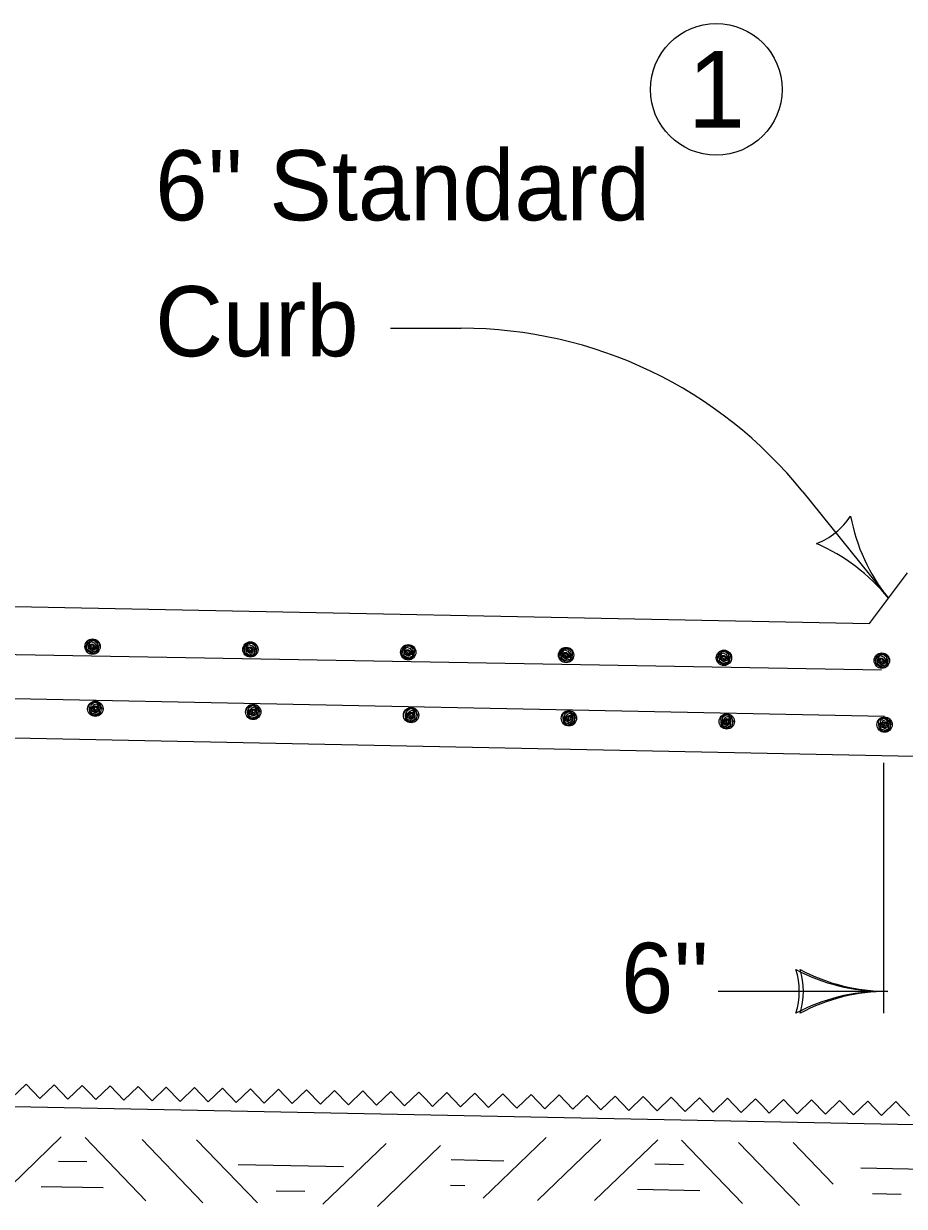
# Model space of a CAD drawing. Extents: x 10133 to 81668, y 7924 to 11018.
# Drawn here: x 11028.4 to 11229.3, y 8273.3 to 8543 of the extents above; entities that cross this region are included whole.
import ezdxf

# ---------------------------------------------------------------- set-up
doc = ezdxf.new("R2010")
doc.units = 0
doc.layers.add('BridgeExistingStructure', color=7, linetype='Continuous')
doc.layers.add('RasterAttachment', color=7, linetype='Continuous')

msp = doc.modelspace()

# ---------------------------------------------------------------- linework, layer by layer
at = {"layer": 'RasterAttachment'}
for p, q in [((11112.11, 8473.58), (11128.23, 8473.58)), ((11206.12, 8436.29), (11225.66, 8412.01)), ((10451.65, 8421.69), (11221.33, 8406.24)), ((11221.33, 8406.24), (11229.99, 8417.79)), ((10468, 8409.1), (11224.07, 8395.72)), ((11044.13, 8400.89), (11044.13, 8400.89)), ((11224.78, 8385.06), (10468.75, 8400.23)), ((11080.13, 8400.25), (11080.13, 8400.25)), ((11116.13, 8399.61), (11116.13, 8399.61)), ((11152.14, 8398.97), (11152.14, 8398.97)), ((10451.65, 8391.68), (11243.49, 8375.79)), ((11044.77, 8388.55), (11044.77, 8388.55)), ((11080.78, 8387.83), (11080.78, 8387.83)), ((11116.78, 8387.11), (11116.78, 8387.11)), ((11152.78, 8386.38), (11152.78, 8386.38)), ((11188.78, 8385.66), (11188.78, 8385.66)), ((11224.78, 8384.94), (11224.78, 8384.94)), ((11189.68, 8383.66), (11189.68, 8383.66)), ((11225.68, 8382.94), (11225.68, 8382.94)), ((11224.54, 8374.45), (11224.54, 8317.37)), ((11224.54, 8322.37), (11186.84, 8322.37)), ((10335.32, 8310), (11315.49, 8290.32)), ((11037.01, 8289.17), (11022.59, 8275.31)), ((11042.42, 8289.06), (11056.27, 8274.63)), ((11055.42, 8288.57), (11069.28, 8274.15)), ((11067.87, 8288.55), (11081.73, 8274.12)), ((11111.09, 8287.68), (11096.66, 8273.82)), ((11147.62, 8289.04), (11133.2, 8275.18)), ((11160.07, 8288.56), (11145.64, 8274.71)), ((11173.08, 8288.53), (11158.65, 8274.67)), ((11178.49, 8288.42), (11192.34, 8274)), ((11191.49, 8287.93), (11205.34, 8273.51)), ((11203.94, 8287.91), (11213.04, 8278.43)), ((11123.53, 8287.2), (11109.11, 8273.35))]:
    msp.add_line(p, q, dxfattribs=at)
for points in [[(11042.52, 8400.89), (11042.81, 8401.47), (11043.13, 8402.38), (11044.07, 8402.52), (11044.88, 8402.36), (11045.61, 8401.75), (11045.5, 8400.88), (11045.34, 8399.96), (11044.59, 8399.55), (11043.81, 8399.5), (11042.82, 8400.08), (11042.76, 8400.75), (11043.03, 8401.66), (11043.64, 8402.4), (11044.52, 8402.34), (11045.2, 8401.72), (11045.24, 8400.89), (11045.03, 8399.98), (11044.51, 8399.86), (11043.88, 8399.7), (11043.13, 8400.16), (11043.18, 8400.83), (11043.33, 8401.59), (11043.78, 8402.13), (11044.53, 8401.82), (11044.96, 8401.22), (11044.96, 8400.45), (11044.53, 8400.27), (11044.06, 8400.05), (11043.46, 8400.45), (11043.35, 8401.02), (11043.64, 8401.52), (11044.21, 8401.53), (11044.6, 8401.25), (11044.72, 8400.72), (11044.5, 8400.48), (11044.18, 8400.35), (11043.73, 8400.64), (11043.65, 8401), (11043.88, 8401.35), (11044.19, 8401.28), (11044.38, 8401.01), (11044.35, 8400.65), (11044.1, 8400.66), (11043.96, 8400.98)], [(11078.52, 8400.25), (11078.81, 8400.83), (11079.13, 8401.74), (11080.07, 8401.88), (11080.88, 8401.73), (11081.62, 8401.11), (11081.51, 8400.24), (11081.34, 8399.32), (11080.59, 8398.91), (11079.81, 8398.86), (11078.82, 8399.44), (11078.76, 8400.11), (11079.03, 8401.03), (11079.65, 8401.76), (11080.52, 8401.7), (11081.2, 8401.09), (11081.25, 8400.26), (11081.03, 8399.34), (11080.51, 8399.22), (11079.88, 8399.06), (11079.14, 8399.52), (11079.18, 8400.19), (11079.34, 8400.95), (11079.79, 8401.49), (11080.54, 8401.18), (11080.96, 8400.59), (11080.96, 8399.81), (11080.54, 8399.63), (11080.06, 8399.41), (11079.47, 8399.81), (11079.35, 8400.39), (11079.64, 8400.88), (11080.21, 8400.9), (11080.6, 8400.61), (11080.72, 8400.09), (11080.5, 8399.84), (11080.18, 8399.71), (11079.74, 8400), (11079.66, 8400.36), (11079.89, 8400.71), (11080.19, 8400.64), (11080.38, 8400.37), (11080.36, 8400.01), (11080.1, 8400.03), (11079.97, 8400.35)], [(11114.53, 8399.62), (11114.82, 8400.2), (11115.13, 8401.1), (11116.07, 8401.25), (11116.89, 8401.09), (11117.62, 8400.47), (11117.51, 8399.6), (11117.34, 8398.69), (11116.59, 8398.27), (11115.82, 8398.22), (11114.83, 8398.8), (11114.77, 8399.48), (11115.03, 8400.39), (11115.65, 8401.12), (11116.52, 8401.06), (11117.2, 8400.45), (11117.25, 8399.62), (11117.04, 8398.71), (11116.51, 8398.59), (11115.88, 8398.42), (11115.14, 8398.89), (11115.19, 8399.55), (11115.34, 8400.32), (11115.79, 8400.86), (11116.54, 8400.55), (11116.96, 8399.95), (11116.96, 8399.18), (11116.54, 8399), (11116.06, 8398.77), (11115.47, 8399.17), (11115.35, 8399.75), (11115.64, 8400.25), (11116.21, 8400.26), (11116.61, 8399.98), (11116.73, 8399.45), (11116.5, 8399.21), (11116.18, 8399.07), (11115.74, 8399.36), (11115.66, 8399.73), (11115.89, 8400.07), (11116.19, 8400), (11116.38, 8399.73), (11116.36, 8399.37), (11116.1, 8399.39), (11115.97, 8399.71)], [(11150.53, 8398.98), (11150.82, 8399.56), (11151.14, 8400.47), (11152.08, 8400.61), (11152.89, 8400.45), (11153.62, 8399.84), (11153.51, 8398.97), (11153.35, 8398.05), (11152.6, 8397.64), (11151.82, 8397.58), (11150.83, 8398.17), (11150.77, 8398.84), (11151.04, 8399.75), (11151.65, 8400.48), (11152.53, 8400.43), (11153.21, 8399.81), (11153.25, 8398.99), (11153.04, 8398.07), (11152.52, 8397.95), (11151.89, 8397.79), (11151.14, 8398.25), (11151.19, 8398.92), (11151.34, 8399.68), (11151.79, 8400.22), (11152.54, 8399.91), (11152.97, 8399.31), (11152.97, 8398.54), (11152.54, 8398.36), (11152.06, 8398.14), (11151.47, 8398.54), (11151.36, 8399.11), (11151.65, 8399.61), (11152.22, 8399.62), (11152.61, 8399.34), (11152.73, 8398.81), (11152.51, 8398.57), (11152.19, 8398.44), (11151.74, 8398.72), (11151.66, 8399.09), (11151.89, 8399.44), (11152.2, 8399.37), (11152.39, 8399.1), (11152.36, 8398.73), (11152.11, 8398.75), (11151.97, 8399.07)], [(11186.53, 8398.34), (11186.82, 8398.92), (11187.14, 8399.83), (11188.08, 8399.97), (11188.89, 8399.82), (11189.63, 8399.2), (11189.52, 8398.33), (11189.35, 8397.41), (11188.6, 8397), (11187.82, 8396.95), (11186.83, 8397.53), (11186.77, 8398.2), (11187.04, 8399.12), (11187.66, 8399.85), (11188.53, 8399.79), (11189.21, 8399.18), (11189.26, 8398.35), (11189.04, 8397.43), (11188.52, 8397.31), (11187.89, 8397.15), (11187.15, 8397.61), (11187.19, 8398.28), (11187.35, 8399.04), (11187.79, 8399.58), (11188.55, 8399.27), (11188.97, 8398.68), (11188.97, 8397.9), (11188.55, 8397.72), (11188.07, 8397.5), (11187.48, 8397.9), (11187.36, 8398.48), (11187.65, 8398.97), (11188.22, 8398.99), (11188.61, 8398.7), (11188.73, 8398.18), (11188.51, 8397.93), (11188.19, 8397.8), (11187.75, 8398.09), (11187.67, 8398.45), (11187.9, 8398.8), (11188.2, 8398.73), (11188.39, 8398.46), (11188.37, 8398.1), (11188.11, 8398.11), (11187.98, 8398.43)], [(11222.54, 8397.71), (11222.83, 8398.29), (11223.14, 8399.19), (11224.08, 8399.34), (11224.9, 8399.18), (11225.63, 8398.56), (11225.52, 8397.69), (11225.35, 8396.78), (11224.61, 8396.36), (11223.83, 8396.31), (11222.84, 8396.89), (11222.78, 8397.57), (11223.05, 8398.48), (11223.66, 8399.21), (11224.53, 8399.15), (11225.22, 8398.54), (11225.26, 8397.71), (11225.05, 8396.8), (11224.52, 8396.68), (11223.89, 8396.51), (11223.15, 8396.98), (11223.2, 8397.64), (11223.35, 8398.41), (11223.8, 8398.94), (11224.55, 8398.64), (11224.98, 8398.04), (11224.97, 8397.26), (11224.55, 8397.09), (11224.07, 8396.86), (11223.48, 8397.26), (11223.36, 8397.84), (11223.65, 8398.34), (11224.22, 8398.35), (11224.62, 8398.06), (11224.74, 8397.54), (11224.51, 8397.3), (11224.19, 8397.16), (11223.75, 8397.45), (11223.67, 8397.82), (11223.9, 8398.16), (11224.21, 8398.09), (11224.39, 8397.82), (11224.37, 8397.46), (11224.11, 8397.48), (11223.98, 8397.8)], [(11046.38, 8386.67), (11046.11, 8387.26), (11045.83, 8388.17), (11044.9, 8388.35), (11044.08, 8388.23), (11043.32, 8387.64), (11043.4, 8386.76), (11043.53, 8385.84), (11044.26, 8385.4), (11045.04, 8385.32), (11046.05, 8385.86), (11046.13, 8386.54), (11045.9, 8387.46), (11045.31, 8388.21), (11044.44, 8388.19), (11043.74, 8387.6), (11043.66, 8386.77), (11043.84, 8385.85), (11044.36, 8385.71), (11044.98, 8385.52), (11045.74, 8385.96), (11045.72, 8386.63), (11045.59, 8387.4), (11045.17, 8387.95), (11044.4, 8387.67), (11043.96, 8387.09), (11043.93, 8386.32), (11044.34, 8386.12), (11044.81, 8385.88), (11045.42, 8386.26), (11045.56, 8386.83), (11045.29, 8387.34), (11044.72, 8387.37), (11044.32, 8387.1), (11044.18, 8386.58), (11044.39, 8386.33), (11044.7, 8386.18), (11045.16, 8386.46), (11045.25, 8386.82), (11045.03, 8387.17), (11044.73, 8387.11), (11044.53, 8386.85), (11044.54, 8386.49), (11044.8, 8386.5), (11044.94, 8386.81)], [(11082.38, 8385.94), (11082.12, 8386.53), (11081.83, 8387.45), (11080.9, 8387.63), (11080.08, 8387.5), (11079.32, 8386.92), (11079.4, 8386.04), (11079.53, 8385.12), (11080.26, 8384.68), (11081.04, 8384.6), (11082.05, 8385.14), (11082.14, 8385.81), (11081.9, 8386.73), (11081.32, 8387.49), (11080.44, 8387.46), (11079.74, 8386.88), (11079.66, 8386.05), (11079.84, 8385.13), (11080.36, 8384.99), (11080.98, 8384.8), (11081.74, 8385.23), (11081.72, 8385.9), (11081.6, 8386.67), (11081.17, 8387.23), (11080.4, 8386.95), (11079.96, 8386.37), (11079.93, 8385.59), (11080.35, 8385.4), (11080.82, 8385.16), (11081.42, 8385.53), (11081.56, 8386.11), (11081.29, 8386.61), (11080.72, 8386.65), (11080.32, 8386.38), (11080.18, 8385.86), (11080.39, 8385.61), (11080.71, 8385.46), (11081.16, 8385.73), (11081.25, 8386.1), (11081.04, 8386.45), (11080.73, 8386.39), (11080.53, 8386.13), (11080.54, 8385.77), (11080.8, 8385.77), (11080.94, 8386.09)], [(11118.38, 8385.22), (11118.12, 8385.81), (11117.83, 8386.73), (11116.9, 8386.91), (11116.08, 8386.78), (11115.33, 8386.19), (11115.4, 8385.32), (11115.53, 8384.4), (11116.27, 8383.95), (11117.04, 8383.87), (11118.05, 8384.42), (11118.14, 8385.09), (11117.91, 8386.01), (11117.32, 8386.77), (11116.44, 8386.74), (11115.74, 8386.15), (11115.66, 8385.33), (11115.84, 8384.41), (11116.36, 8384.27), (11116.98, 8384.08), (11117.74, 8384.51), (11117.72, 8385.18), (11117.6, 8385.95), (11117.17, 8386.5), (11116.41, 8386.22), (11115.96, 8385.64), (11115.93, 8384.87), (11116.35, 8384.68), (11116.82, 8384.43), (11117.43, 8384.81), (11117.56, 8385.38), (11117.29, 8385.89), (11116.72, 8385.92), (11116.32, 8385.66), (11116.18, 8385.14), (11116.39, 8384.88), (11116.71, 8384.74), (11117.16, 8385.01), (11117.25, 8385.37), (11117.04, 8385.73), (11116.73, 8385.67), (11116.53, 8385.4), (11116.54, 8385.04), (11116.8, 8385.05), (11116.95, 8385.36)], [(11154.39, 8384.5), (11154.12, 8385.09), (11153.84, 8386.01), (11152.9, 8386.18), (11152.08, 8386.06), (11151.33, 8385.47), (11151.41, 8384.6), (11151.54, 8383.67), (11152.27, 8383.23), (11153.04, 8383.15), (11154.06, 8383.69), (11154.14, 8384.37), (11153.91, 8385.29), (11153.32, 8386.04), (11152.45, 8386.02), (11151.74, 8385.43), (11151.66, 8384.6), (11151.84, 8383.68), (11152.36, 8383.54), (11152.99, 8383.36), (11153.75, 8383.79), (11153.73, 8384.46), (11153.6, 8385.23), (11153.17, 8385.78), (11152.41, 8385.5), (11151.96, 8384.92), (11151.93, 8384.15), (11152.35, 8383.95), (11152.82, 8383.71), (11153.43, 8384.09), (11153.57, 8384.66), (11153.29, 8385.17), (11152.73, 8385.2), (11152.32, 8384.93), (11152.18, 8384.41), (11152.4, 8384.16), (11152.71, 8384.02), (11153.16, 8384.29), (11153.26, 8384.65), (11153.04, 8385), (11152.73, 8384.94), (11152.54, 8384.68), (11152.55, 8384.32), (11152.8, 8384.33), (11152.95, 8384.64)], [(11190.39, 8383.77), (11190.12, 8384.37), (11189.84, 8385.28), (11188.9, 8385.46), (11188.09, 8385.34), (11187.33, 8384.75), (11187.41, 8383.87), (11187.54, 8382.95), (11188.27, 8382.51), (11189.04, 8382.43), (11190.06, 8382.97), (11190.14, 8383.64), (11189.91, 8384.57), (11189.32, 8385.32), (11188.45, 8385.29), (11187.74, 8384.71), (11187.66, 8383.88), (11187.84, 8382.96), (11188.36, 8382.82), (11188.99, 8382.63), (11189.75, 8383.07), (11189.73, 8383.74), (11189.6, 8384.5), (11189.17, 8385.06), (11188.41, 8384.78), (11187.96, 8384.2), (11187.93, 8383.43), (11188.35, 8383.23), (11188.82, 8382.99), (11189.43, 8383.37), (11189.57, 8383.94), (11189.29, 8384.44), (11188.73, 8384.48), (11188.32, 8384.21), (11188.18, 8383.69), (11188.4, 8383.44), (11188.71, 8383.29), (11189.17, 8383.56), (11189.26, 8383.93), (11189.04, 8384.28), (11188.73, 8384.22), (11188.54, 8383.96), (11188.55, 8383.6), (11188.8, 8383.61), (11188.95, 8383.92)], [(11226.39, 8383.05), (11226.12, 8383.64), (11225.84, 8384.56), (11224.91, 8384.74), (11224.09, 8384.61), (11223.33, 8384.02), (11223.41, 8383.15), (11223.54, 8382.23), (11224.27, 8381.79), (11225.05, 8381.71), (11226.06, 8382.25), (11226.14, 8382.92), (11225.91, 8383.84), (11225.32, 8384.6), (11224.45, 8384.57), (11223.74, 8383.98), (11223.67, 8383.16), (11223.85, 8382.24), (11224.37, 8382.1), (11224.99, 8381.91), (11225.75, 8382.34), (11225.73, 8383.01), (11225.6, 8383.78), (11225.18, 8384.34), (11224.41, 8384.06), (11223.97, 8383.48), (11223.94, 8382.7), (11224.35, 8382.51), (11224.82, 8382.27), (11225.43, 8382.64), (11225.57, 8383.21), (11225.3, 8383.72), (11224.73, 8383.76), (11224.33, 8383.49), (11224.19, 8382.97), (11224.4, 8382.72), (11224.71, 8382.57), (11225.17, 8382.84), (11225.26, 8383.21), (11225.04, 8383.56), (11224.74, 8383.5), (11224.54, 8383.24), (11224.55, 8382.88), (11224.81, 8382.88), (11224.95, 8383.2)], [(11025.7, 8298.06), (11028.97, 8301.2), (11032.1, 8297.93), (11035.37, 8301.07), (11038.5, 8297.8), (11041.77, 8300.94), (11043.33, 8299.31)], [(11043.33, 8299.31), (11044.9, 8297.68), (11048.16, 8300.81), (11051.3, 8297.55), (11054.56, 8300.68), (11057.7, 8297.42), (11060.96, 8300.55), (11064.1, 8297.29), (11067.36, 8300.43), (11070.5, 8297.16), (11073.76, 8300.3), (11076.89, 8297.03), (11080.16, 8300.17), (11083.29, 8296.91), (11086.56, 8300.04), (11089.69, 8296.78), (11092.96, 8299.91), (11096.09, 8296.65), (11099.35, 8299.78), (11102.49, 8296.52), (11105.75, 8299.65), (11108.89, 8296.39), (11112.15, 8299.53), (11115.29, 8296.26), (11118.55, 8299.4), (11120.12, 8297.77)], [(11120.12, 8297.77), (11121.69, 8296.13), (11124.95, 8299.27), (11128.08, 8296.01), (11131.35, 8299.14), (11134.48, 8295.88), (11137.75, 8299.01), (11140.88, 8295.75), (11144.15, 8298.88), (11147.28, 8295.62), (11150.54, 8298.76), (11153.68, 8295.49), (11156.94, 8298.63), (11160.08, 8295.36), (11163.34, 8298.5), (11166.48, 8295.24), (11169.74, 8298.37), (11172.88, 8295.11), (11176.14, 8298.24), (11179.27, 8294.98), (11182.54, 8298.11), (11185.67, 8294.85), (11188.94, 8297.99), (11192.07, 8294.72), (11195.33, 8297.86), (11196.9, 8296.23)], [(11196.9, 8296.23), (11198.47, 8294.59), (11201.73, 8297.73), (11204.87, 8294.47), (11208.13, 8297.6), (11211.27, 8294.34), (11214.53, 8297.47), (11217.67, 8294.21), (11220.93, 8297.34), (11224.06, 8294.08), (11227.33, 8297.22), (11230.46, 8293.95)], [(11036.34, 8283.68), (11042.87, 8283.55)], [(11077.34, 8282.88), (11101.4, 8282.4)], [(11125.91, 8284), (11137.93, 8283.76)], [(11172.41, 8283.04), (11178.94, 8282.91)], [(11219.4, 8282.12), (11237.47, 8281.76)], [(11032.39, 8277.9), (11046.58, 8277.62)], [(11085.99, 8276.91), (11092.52, 8276.78)], [(11125.79, 8278.2), (11129.05, 8278.13)], [(11168.46, 8277.26), (11182.65, 8276.98)], [(11222.06, 8276.27), (11228.59, 8276.14)]]:
    msp.add_lwpolyline(points, dxfattribs=at)
for centre, radius in [((11186.39, 8528.03), 15), ((11044.13, 8400.97), 1.75), ((11080.14, 8400.33), 1.75), ((11116.14, 8399.69), 1.75), ((11152.14, 8399.06), 1.75), ((11188.14, 8398.42), 1.75), ((11224.15, 8397.78), 1.75), ((11044.77, 8386.8), 1.75), ((11080.78, 8386.08), 1.75), ((11116.78, 8385.36), 1.75), ((11152.78, 8384.63), 1.75), ((11188.78, 8383.91), 1.75), ((11224.78, 8383.19), 1.75)]:
    msp.add_circle(centre, radius, dxfattribs=at)
for centre, radius, start, end in [((11128.23, 8373.58), 100, 38.8378, 90), ((11203.31, 8439.77), 16.42, 291.1042, 326.5709), ((11258.77, 8438.67), 42.5, 190.7651, 218.8375), ((11192.56, 8385.36), 42.5, 38.8375, 66.91), ((11188.91, 8322.37), 16.42, 342.2666, 17.7333), ((11224.54, 8364.87), 42.5, 241.9275, 270), ((11189.86, 8322.37), 16.42, 342.2666, 17.7333), ((11225.49, 8364.87), 42.5, 241.9275, 270), ((11224.54, 8279.87), 42.5, 90, 118.0725), ((11225.49, 8279.87), 42.5, 90, 118.0725)]:
    msp.add_arc(centre, radius, start, end, dxfattribs=at)

# ---------------------------------------------------------------- texts
at = {"layer": 'BridgeExistingStructure'}
for s, height, p in [('1', 17.5, (11179.92, 8519.28)), ("6'' Standard", 16, (11058.43, 8498.18)), ('Curb', 16, (11058.43, 8467.18)), ("6''", 16, (11164.68, 8317.45))]:
    msp.add_text(s, height=height, dxfattribs=at).set_placement(p)

doc.saveas('drawing.dxf')
